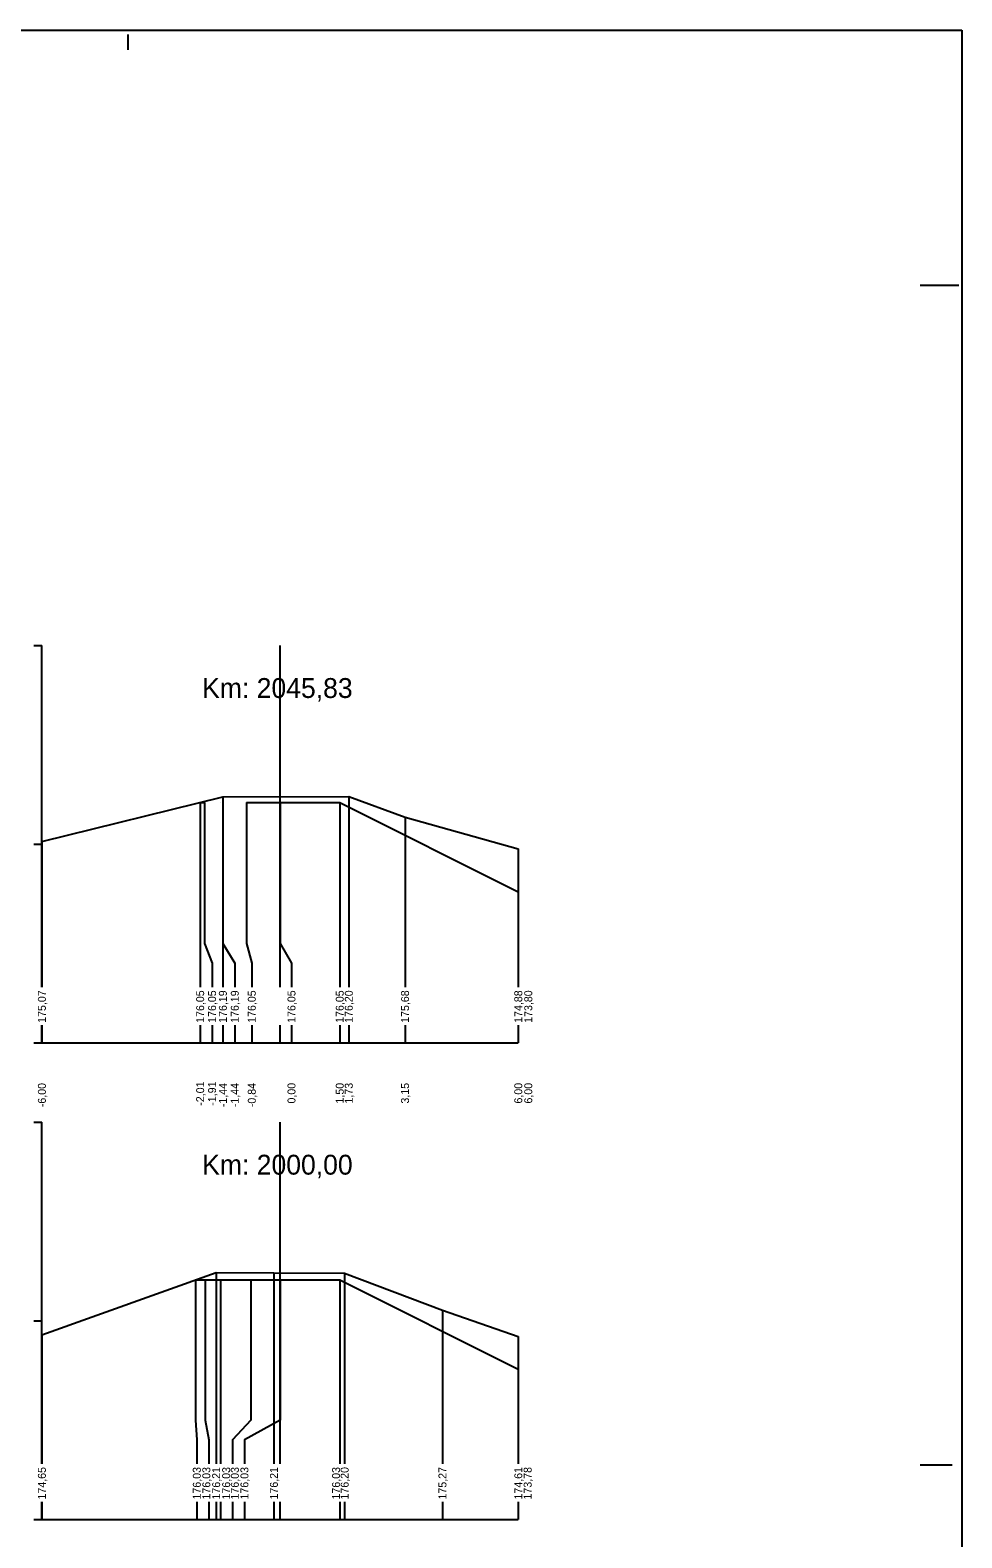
# Model space of a CAD drawing. Extents: x -614174 to -599765, y -1185887 to -1181080.
# Drawn here: x -608656 to -608632.53, y -1184491.25 to -1184453.29 of the extents above; entities that cross this region are included whole.
import ezdxf

# ---------------------------------------------------------------- set-up
doc = ezdxf.new("R2010")
doc.units = 0
for name, color, linetype in [('11', 7, 'Continuous'), ('16', 7, 'Continuous'), ('21', 7, 'Continuous'), ('28', 7, 'Continuous'), ('59', 7, 'Continuous'), ('8', 7, 'Continuous'), ('návrh', 7, 'Continuous')]:
    doc.layers.add(name, color=color, linetype=linetype)

msp = doc.modelspace()

# ---------------------------------------------------------------- linework, layer by layer
for points in [[(-608655.705, -1184473.717), (-608651.146, -1184472.592), (-608651.145, -1184472.592), (-608647.975, -1184472.58), (-608646.558, -1184473.105), (-608643.705, -1184473.903)], [(-608651.718, -1184472.733), (-608651.613, -1184472.733)], [(-608651.203, -1184472.733), (-608651.203, -1184472.733)], [(-608650.549, -1184472.733), (-608649.703, -1184472.733), (-608648.203, -1184472.733), (-608643.705, -1184474.983)], [(-608649.703, -1184472.733), (-608649.703, -1184472.733)], [(-608648.203, -1184472.733), (-608648.203, -1184472.733)], [(-608655.705, -1184486.134), (-608651.315, -1184484.568), (-608649.86, -1184484.572), (-608648.079, -1184484.583), (-608645.615, -1184485.512), (-608643.705, -1184486.177)], [(-608651.838, -1184484.754), (-608651.591, -1184484.754), (-608651.203, -1184484.754), (-608650.444, -1184484.754), (-608649.703, -1184484.754), (-608648.203, -1184484.754), (-608643.705, -1184487.003)], [(-608651.203, -1184484.754), (-608651.203, -1184484.754), (-608651.203, -1184484.754)], [(-608649.703, -1184484.754), (-608649.703, -1184484.754), (-608649.703, -1184484.754)], [(-608648.203, -1184484.754), (-608648.203, -1184484.754), (-608648.203, -1184484.754)]]:
    msp.add_lwpolyline(points)
at = {"layer": '11'}
for points in [[(-608651.718, -1184472.733), (-608651.718, -1184476.282), (-608651.718, -1184476.782), (-608651.718, -1184477.384)], [(-608651.613, -1184472.733), (-608651.613, -1184476.282), (-608651.418, -1184476.782), (-608651.418, -1184477.384)], [(-608651.146, -1184472.592), (-608651.146, -1184476.282), (-608651.146, -1184476.782), (-608651.146, -1184477.384)], [(-608651.145, -1184472.592), (-608651.145, -1184476.282), (-608650.846, -1184476.782), (-608650.846, -1184477.384)], [(-608650.549, -1184472.733), (-608650.549, -1184476.282), (-608650.418, -1184476.782), (-608650.418, -1184477.384)], [(-608649.703, -1184472.733), (-608649.703, -1184476.282), (-608649.418, -1184476.782), (-608649.418, -1184477.384)], [(-608648.203, -1184472.733), (-608648.203, -1184476.282), (-608648.203, -1184476.782), (-608648.203, -1184477.384)], [(-608647.975, -1184472.58), (-608647.975, -1184476.282), (-608647.975, -1184476.782), (-608647.975, -1184477.384)], [(-608646.558, -1184473.105), (-608646.558, -1184476.282), (-608646.558, -1184476.782), (-608646.558, -1184477.384)], [(-608655.705, -1184473.717), (-608655.705, -1184476.282), (-608655.705, -1184476.782), (-608655.705, -1184477.384)], [(-608643.705, -1184473.903), (-608643.705, -1184476.282), (-608643.705, -1184476.782), (-608643.705, -1184477.384)], [(-608643.705, -1184474.983), (-608643.705, -1184476.282), (-608643.705, -1184476.782), (-608643.705, -1184477.384)], [(-608655.705, -1184478.342), (-608655.705, -1184478.782)], [(-608651.718, -1184478.342), (-608651.718, -1184478.782)], [(-608651.418, -1184478.342), (-608651.418, -1184478.782)], [(-608651.146, -1184478.342), (-608651.146, -1184478.782)], [(-608650.846, -1184478.342), (-608650.846, -1184478.782)], [(-608650.418, -1184478.342), (-608650.418, -1184478.782)], [(-608649.418, -1184478.342), (-608649.418, -1184478.782)], [(-608648.203, -1184478.342), (-608648.203, -1184478.782)], [(-608647.975, -1184478.342), (-608647.975, -1184478.782)], [(-608646.558, -1184478.342), (-608646.558, -1184478.782)], [(-608643.705, -1184478.342), (-608643.705, -1184478.782)], [(-608643.705, -1184478.342), (-608643.705, -1184478.782)], [(-608651.315, -1184484.568), (-608651.315, -1184488.282), (-608651.315, -1184488.782), (-608651.315, -1184489.384)], [(-608649.86, -1184484.572), (-608649.86, -1184488.282), (-608649.86, -1184488.782), (-608649.86, -1184489.384)], [(-608648.079, -1184484.583), (-608648.079, -1184488.282), (-608648.079, -1184488.782), (-608648.079, -1184489.384)], [(-608651.838, -1184484.754), (-608651.838, -1184488.282), (-608651.803, -1184488.782), (-608651.803, -1184489.384)], [(-608651.591, -1184484.754), (-608651.591, -1184488.282), (-608651.503, -1184488.782), (-608651.503, -1184489.384)], [(-608651.203, -1184484.754), (-608651.203, -1184488.282), (-608651.203, -1184488.782), (-608651.203, -1184489.384)], [(-608650.444, -1184484.754), (-608650.444, -1184488.282), (-608650.903, -1184488.782), (-608650.903, -1184489.384)], [(-608649.703, -1184484.754), (-608649.703, -1184488.282), (-608650.603, -1184488.782), (-608650.603, -1184489.384)], [(-608648.203, -1184484.754), (-608648.203, -1184488.282), (-608648.203, -1184488.782), (-608648.203, -1184489.384)], [(-608645.615, -1184485.512), (-608645.615, -1184488.282), (-608645.615, -1184488.782), (-608645.615, -1184489.384)], [(-608655.705, -1184486.134), (-608655.705, -1184488.282), (-608655.705, -1184488.782), (-608655.705, -1184489.384)], [(-608643.705, -1184486.177), (-608643.705, -1184488.282), (-608643.705, -1184488.782), (-608643.705, -1184489.384)], [(-608643.705, -1184487.003), (-608643.705, -1184488.282), (-608643.705, -1184488.782), (-608643.705, -1184489.384)], [(-608655.705, -1184490.342), (-608655.705, -1184490.782)], [(-608651.803, -1184490.342), (-608651.803, -1184490.782)], [(-608651.503, -1184490.342), (-608651.503, -1184490.782)], [(-608651.315, -1184490.342), (-608651.315, -1184490.782)], [(-608651.203, -1184490.342), (-608651.203, -1184490.782)], [(-608650.903, -1184490.342), (-608650.903, -1184490.782)], [(-608650.603, -1184490.342), (-608650.603, -1184490.782)], [(-608649.86, -1184490.342), (-608649.86, -1184490.782)], [(-608648.203, -1184490.342), (-608648.203, -1184490.782)], [(-608648.079, -1184490.342), (-608648.079, -1184490.782)], [(-608645.615, -1184490.342), (-608645.615, -1184490.782)], [(-608643.705, -1184490.342), (-608643.705, -1184490.782)], [(-608643.705, -1184490.342), (-608643.705, -1184490.782)]]:
    msp.add_lwpolyline(points, dxfattribs=at)
at = {"layer": '16'}
for p, q in [((-608655.705, -1184478.782), (-608643.705, -1184478.782)), ((-608655.705, -1184490.782), (-608643.705, -1184490.782))]:
    msp.add_line(p, q, dxfattribs=at)
at = {"layer": '21'}
for p, q in [((-608655.905, -1184468.782), (-608655.705, -1184468.782)), ((-608655.905, -1184473.782), (-608655.705, -1184473.782)), ((-608655.905, -1184478.782), (-608655.705, -1184478.782)), ((-608655.905, -1184480.782), (-608655.705, -1184480.782)), ((-608655.905, -1184485.782), (-608655.705, -1184485.782)), ((-608655.905, -1184490.782), (-608655.705, -1184490.782))]:
    msp.add_line(p, q, dxfattribs=at)
at = {"layer": '28'}
for p, q in [((-608649.705, -1184477.384), (-608649.705, -1184468.782)), ((-608649.705, -1184478.782), (-608649.705, -1184478.342)), ((-608649.705, -1184489.384), (-608649.705, -1184480.782)), ((-608649.705, -1184490.782), (-608649.705, -1184490.342))]:
    msp.add_line(p, q, dxfattribs=at)
at = {"layer": '8'}
for p, q in [((-608655.705, -1184477.384), (-608655.705, -1184468.782)), ((-608655.705, -1184478.782), (-608655.705, -1184478.342)), ((-608655.705, -1184489.384), (-608655.705, -1184480.782)), ((-608655.705, -1184490.782), (-608655.705, -1184490.342))]:
    msp.add_line(p, q, dxfattribs=at)
at = {"layer": 'návrh'}
for p, q in [((-608716.532, -1184453.291), (-608632.532, -1184453.291)), ((-608653.532, -1184453.783), (-608653.532, -1184453.402)), ((-608632.532, -1184453.291), (-608632.532, -1184519.11)), ((-608633.584, -1184459.71), (-608632.612, -1184459.71)), ((-608633.584, -1184489.41), (-608632.779, -1184489.41))]:
    msp.add_line(p, q, dxfattribs=at)

# ---------------------------------------------------------------- texts
for p in [(-608651.719, -1184472.734), (-608651.838, -1184484.755)]:
    msp.add_text('+', height=0.001).set_placement(p)
at = {"layer": '16'}
for s, p in [('175,07', (-608655.605, -1184478.282)), ('176,05', (-608651.618, -1184478.282)), ('176,05', (-608651.318, -1184478.282)), ('176,19', (-608651.046, -1184478.282)), ('176,19', (-608650.746, -1184478.282)), ('176,05', (-608650.318, -1184478.282)), ('176,05', (-608649.318, -1184478.282)), ('176,05', (-608648.103, -1184478.282)), ('176,20', (-608647.875, -1184478.282)), ('175,68', (-608646.458, -1184478.282)), ('174,88', (-608643.605, -1184478.282)), ('173,80', (-608643.353, -1184478.282)), ('174,65', (-608655.605, -1184490.282)), ('176,03', (-608651.703, -1184490.282)), ('176,03', (-608651.463, -1184490.282)), ('176,21', (-608651.215, -1184490.282)), ('176,03', (-608650.963, -1184490.282)), ('176,03', (-608650.745, -1184490.282)), ('176,03', (-608650.503, -1184490.282)), ('176,21', (-608649.76, -1184490.282)), ('176,03', (-608648.196, -1184490.282)), ('176,20', (-608647.979, -1184490.282)), ('175,27', (-608645.515, -1184490.282)), ('174,61', (-608643.605, -1184490.282)), ('173,78', (-608643.369, -1184490.282))]:
    msp.add_text(s, height=0.2, rotation=90, dxfattribs=at).set_placement(p)
at = {"layer": '28'}
for s, p in [('Km: 2045,83', (-608651.669, -1184470.103)), ('Km: 2000,00', (-608651.668, -1184482.103))]:
    msp.add_text(s, height=0.5, dxfattribs=at).set_placement(p)
at = {"layer": '59'}
for s, p in [('-6,00', (-608655.605, -1184480.406)), ('-2,01', (-608651.618, -1184480.368)), ('-1,91', (-608651.318, -1184480.368)), ('-1,44', (-608651.046, -1184480.405)), ('-1,44', (-608650.746, -1184480.405)), ('-0,84', (-608650.318, -1184480.405)), ('0,00', (-608649.318, -1184480.313)), ('1,50', (-608648.103, -1184480.313)), ('1,73', (-608647.875, -1184480.313)), ('3,15', (-608646.458, -1184480.315)), ('6,00', (-608643.605, -1184480.313)), ('6,00', (-608643.353, -1184480.313))]:
    msp.add_text(s, height=0.2, rotation=90, dxfattribs=at).set_placement(p)

doc.saveas('drawing.dxf')
